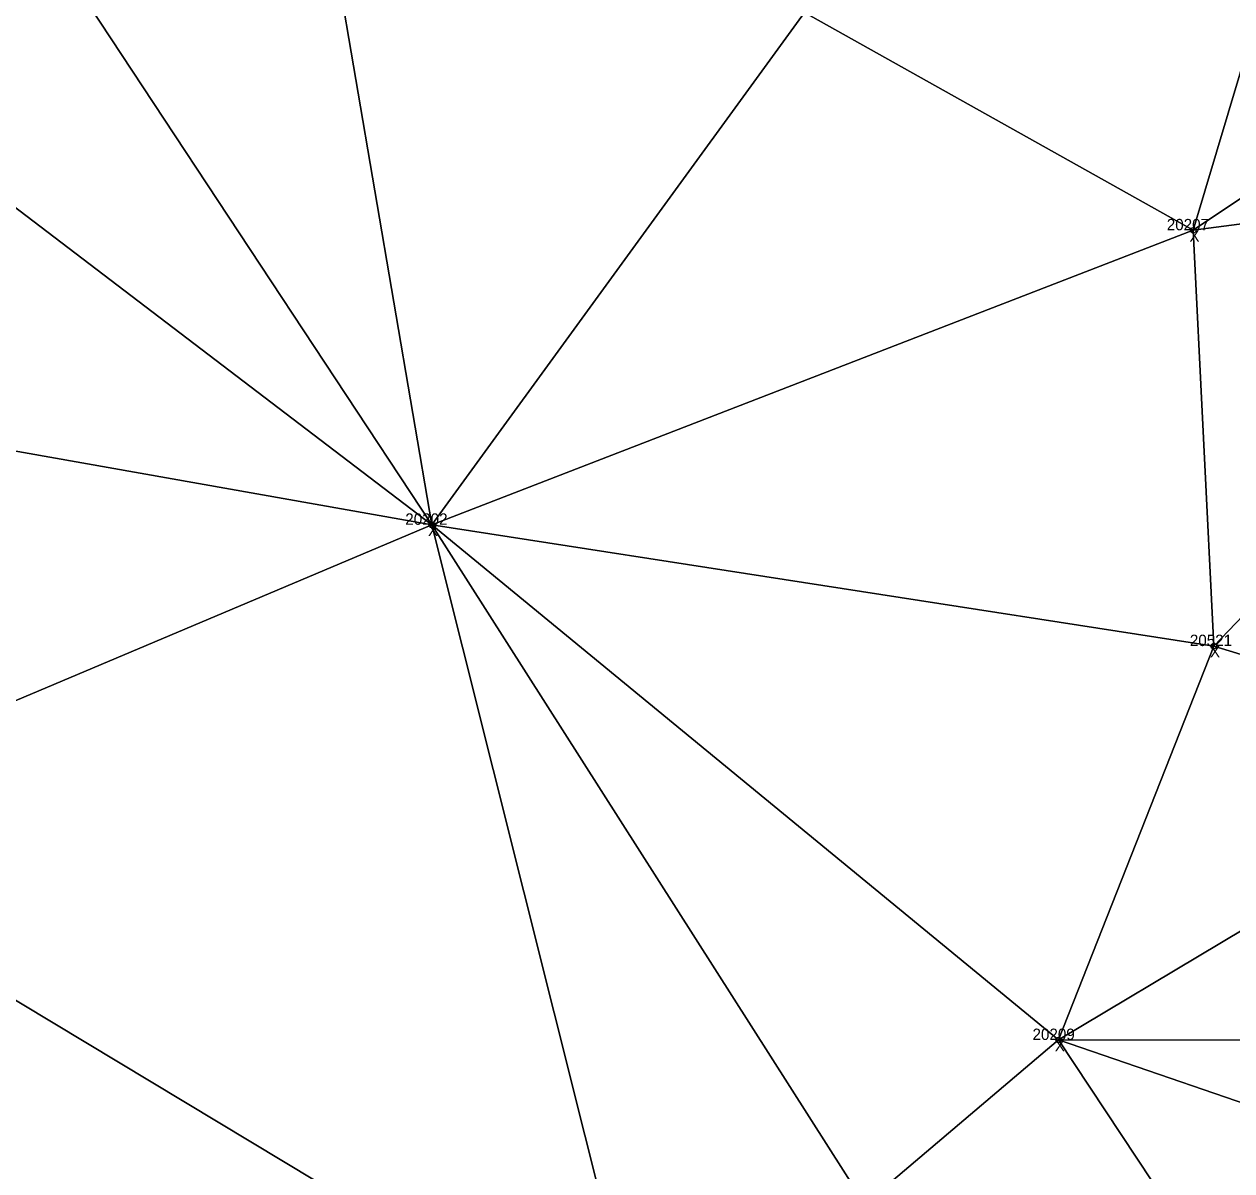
# Model space of a CAD drawing. Extents: x 1966740 to 1969291, y 1117379 to 1118460.
# Drawn here: x 1967626.6 to 1967732.8, y 1117655.1 to 1117756 of the extents above; entities that cross this region are included whole.
import ezdxf

# ---------------------------------------------------------------- set-up
doc = ezdxf.new("R2010")
doc.units = 0
for name, color, linetype in [('Level 30', 7, 'Continuous'), ('Level 35', 7, 'Continuous'), ('Level 52', 7, 'Continuous'), ('Level 62', 7, 'Continuous')]:
    doc.layers.add(name, color=color, linetype=linetype)

msp = doc.modelspace()

# ---------------------------------------------------------------- linework, layer by layer
at = {"layer": 'Level 30'}
for centre in [(1967729.44, 1117737.88), (1967662.45, 1117711.98), (1967731.25, 1117701.31), (1967717.6, 1117666.66)]:
    msp.add_circle(centre, 0.25, dxfattribs=at)
at = {"layer": 'Level 35'}
for points in [[(1967695.23, 1117757.03), (1967742.85, 1117782.8), (1967729.44, 1117737.88)], [(1967729.44, 1117737.88), (1967742.85, 1117782.8), (1967746.98, 1117749.58)], [(1967628.56, 1117763.37), (1967652.44, 1117770.75), (1967662.45, 1117711.98)], [(1967652.44, 1117770.75), (1967695.23, 1117757.03), (1967662.45, 1117711.98)], [(1967604.68, 1117755.99), (1967628.56, 1117763.37), (1967662.45, 1117711.98)], [(1967662.45, 1117711.98), (1967695.23, 1117757.03), (1967729.44, 1117737.88)], [(1967583.14, 1117726.03), (1967604.68, 1117755.99), (1967662.45, 1117711.98)], [(1967729.44, 1117737.88), (1967746.98, 1117749.58), (1967771.52, 1117743.36)], [(1967729.44, 1117737.88), (1967771.52, 1117743.36), (1967731.25, 1117701.31)], [(1967731.25, 1117701.31), (1967771.52, 1117743.36), (1967760.59, 1117692.36)], [(1967662.45, 1117711.98), (1967729.44, 1117737.88), (1967731.25, 1117701.31)], [(1967583.14, 1117726.03), (1967662.45, 1117711.98), (1967600.11, 1117685.65)], [(1967600.11, 1117685.65), (1967662.45, 1117711.98), (1967681.31, 1117636.77)], [(1967662.45, 1117711.98), (1967731.25, 1117701.31), (1967717.6, 1117666.66)], [(1967662.45, 1117711.98), (1967717.6, 1117666.66), (1967700.55, 1117652.23)], [(1967662.45, 1117711.98), (1967700.55, 1117652.23), (1967681.31, 1117636.77)], [(1967717.6, 1117666.66), (1967731.25, 1117701.31), (1967760.59, 1117692.36)], [(1967717.6, 1117666.66), (1967760.59, 1117692.36), (1967769.76, 1117666.62)], [(1967600.11, 1117685.65), (1967681.31, 1117636.77), (1967676.25, 1117583.97)], [(1967700.55, 1117652.23), (1967717.6, 1117666.66), (1967731.36, 1117645.86)], [(1967717.6, 1117666.66), (1967769.76, 1117666.62), (1967762.68, 1117651.19)], [(1967717.6, 1117666.66), (1967762.68, 1117651.19), (1967731.36, 1117645.86)]]:
    msp.add_lwpolyline(points, close=True, dxfattribs=at)

# ---------------------------------------------------------------- texts
at = {"layer": 'Level 52'}
for s, p in [('20207', (1967727.11, 1117737.88)), ('20202', (1967660.13, 1117711.98)), ('20521', (1967729.14, 1117701.31)), ('20209', (1967715.3, 1117666.66))]:
    msp.add_text(s, height=1, dxfattribs=at).set_placement(p)
at = {"layer": 'Level 62'}
for p in [(1967729.1, 1117736.88), (1967662.12, 1117710.98), (1967730.91, 1117700.31), (1967717.26, 1117665.66)]:
    msp.add_text('X', height=1, dxfattribs=at).set_placement(p)

doc.saveas('drawing.dxf')
